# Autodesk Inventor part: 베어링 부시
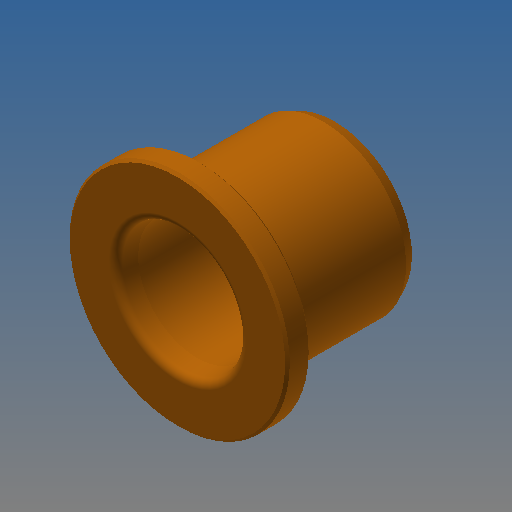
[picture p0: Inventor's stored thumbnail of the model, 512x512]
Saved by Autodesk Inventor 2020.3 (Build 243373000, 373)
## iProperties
Created: 2022-03
Part Number: 베어링 부시
Material: 황동, 연질
Document SubType Name: Modeling
Designer: mdu-01
Density: 1 g/cm^3
Appearance: 주황색
Author: mdu-01
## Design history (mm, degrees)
sketch "스케치1"
  geometry: L1 (0, 0)-(0, -20); L2 (7.941, 0)-(14, 0); L3 (14, 0)-(14, -3); L4 (14, -3)-(10.5, -3); L5 (10.5, -3)-(10.5, -18.6); L6 (9.844, -20)-(7.606, -20); L7 (7.5, -2.5)-(7.5, -19.4); L8 (7.5, -2.5)-(7.941, 0); L9 (7.5, -19.4)-(7.606, -20); L10 (10.5, -18.6)-(9.844, -20)
  constraints: 20 end point, 3 perpendicular, 2 horizontal alignment, 2 parallel, 1 horizontal, 1 vertical
  dimensions: "d0" = 21 diameter of L5 L1; "d2" = 28 diameter of L3 L1; "d3" = 20 distance of L1.start L1.end; "d4" = 3 distance of L2.end L3.end; "d5" = 15 diameter of L7 L1; "d6" = 10 deg angle of L7 L9; "d7" = 0.6 distance from line of L7.end L6; "d8" = 1.4 vertical distance of L5.end L6.start; "d9" = 25.0978 deg angle of L5 L10; "d10" = 10 deg angle of L7 L8; "d11" = 2.5 vertical distance of L7.start L2.start
revolve "회전1" sketch "스케치1" stored, may be unused: angle "d12" = 90 deg
chamfer "모따기1" distance "d13" = 0.3; stored, may be unused: second distance "d14" = 2, angle "d15" = 45 deg
fillet "모깎기1" dims "d16" = 0.3, "d17" = 1
node "솔리드1"
